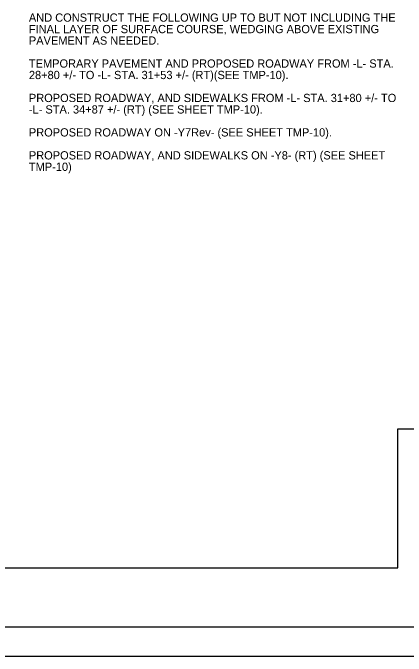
# Model space of a CAD drawing. Extents: x 764226 to 769781, y 650021 to 652521.
# Drawn here: x 767214 to 767548, y 651421 to 651968 of the extents above; entities that cross this region are included whole.
import ezdxf

# ---------------------------------------------------------------- set-up
doc = ezdxf.new("R2010")
doc.units = 0
for name, color, linetype in [('Default', 7, 'Continuous'), ('DEV BORDER CELL', 7, 'Continuous'), ('Scratch_Level_0', 7, 'Continuous'), ('Sheet Plot Border Outside CELL', 7, 'Continuous')]:
    doc.layers.add(name, color=color, linetype=linetype)

msp = doc.modelspace()

# ---------------------------------------------------------------- linework, layer by layer
at = {"layer": 'DEV BORDER CELL'}
msp.add_lwpolyline([(768112.34, 652496.28), (766612.34, 652496.28), (766612.34, 651446.28), (768112.34, 651446.28)], close=True, dxfattribs=at)
at = {"layer": 'Scratch_Level_0'}
msp.add_lwpolyline([(768062.34, 652446.28), (766662.34, 652446.28), (766662.34, 651496.28), (767541.19, 651496.28), (767541.19, 651614.55), (768062.34, 651614.55)], close=True, dxfattribs=at)
at = {"layer": 'Sheet Plot Border Outside CELL'}
msp.add_lwpolyline([(766449.34, 651421.28), (768137.34, 651421.28), (768137.34, 652521.28), (766449.34, 652521.28)], close=True, dxfattribs=at)

# ---------------------------------------------------------------- texts
at = {"layer": 'Default'}
for s, p in [('AND CONSTRUCT THE FOLLOWING UP TO BUT NOT INCLUDING THE ', (767227.87, 651960.4)), ('FINAL LAYER OF SURFACE COURSE, WEDGING ABOVE EXISTING ', (767227.87, 651950.65)), ('PAVEMENT AS NEEDED.', (767227.87, 651940.89)), ('TEMPORARY PAVEMENT AND PROPOSED ROADWAY FROM -L- STA. ', (767227.87, 651921.38)), ('28+80 +/- TO -L- STA. 31+53 +/- (RT)(SEE TMP-10).', (767227.87, 651911.63)), ('PROPOSED ROADWAY, AND SIDEWALKS FROM -L- STA. 31+80 +/- TO', (767227.87, 651892.12)), ('-L- STA. 34+87 +/- (RT) (SEE SHEET TMP-10). ', (767227.87, 651882.37)), ('PROPOSED ROADWAY ON -Y7Rev- (SEE SHEET TMP-10).', (767227.87, 651862.86)), ('PROPOSED ROADWAY, AND SIDEWALKS ON -Y8- (RT) (SEE SHEET ', (767227.87, 651843.35)), ('TMP-10) ', (767227.87, 651833.6))]:
    msp.add_text(s, height=7, rotation=359.9999, dxfattribs=at).set_placement(p)

doc.saveas('drawing.dxf')
